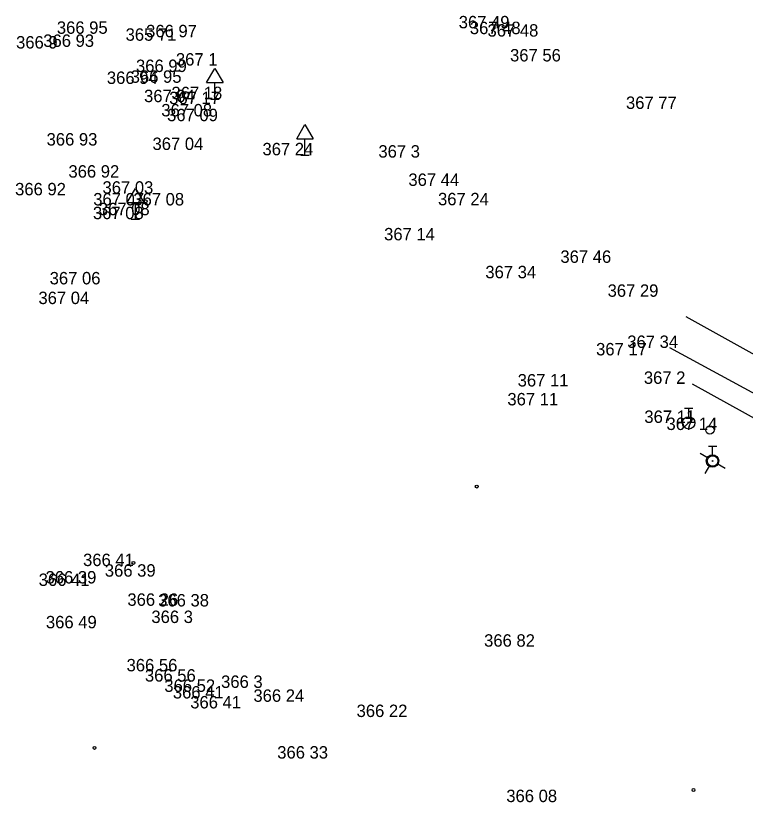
# Model space of a CAD drawing. Extents: x -688316 to -688024, y -973785 to -973591.
# Drawn here: x -688235.65 to -688191.59, y -973650.8 to -973603.28 of the extents above; entities that cross this region are included whole.
import ezdxf

# ---------------------------------------------------------------- set-up
doc = ezdxf.new("R2010")
doc.units = 0
for name, color, linetype in [('Vrstva 10', 7, 'Continuous'), ('Vrstva 28_Verejne osvetleni', 7, 'Continuous'), ('Vrstva 3', 7, 'Continuous'), ('Vrstva 34', 7, 'Continuous'), ('Vrstva 58', 7, 'Continuous'), ('Vrstva 9', 7, 'Continuous')]:
    doc.layers.add(name, color=color, linetype=linetype)

# ---------------------------------------------------------------- blocks, each defined once
blk = doc.blocks.new('B_NESP')
at = {"layer": 'Vrstva 58'}
blk.add_circle((0, 0), 0.875, dxfattribs=at)
blk = doc.blocks.new('DZ')
at = {"layer": 'Vrstva 34'}
for p, q in [((-5, 10), (0, 18.5)), ((0, 18.5), (5, 10)), ((-5, 10), (5, 10)), ((0, 0), (0, 10)), ((-2.49, 0), (2.49, 0))]:
    blk.add_line(p, q, dxfattribs=at)
blk = doc.blocks.new('HYN')
at = {"layer": 'Vrstva 28_Verejne osvetleni'}
for p, q in [((-2.5, 8.99), (2.5, 8.99)), ((0, 3.75), (0, 8.99))]:
    blk.add_line(p, q, dxfattribs=at)
blk.add_circle((0, 0), 3.75, dxfattribs=at)
blk = doc.blocks.new('SV')
at = {"layer": 'Vrstva 28_Verejne osvetleni'}
blk.add_circle((0, 0), 2.5, dxfattribs=at)
blk = doc.blocks.new('HYP')
at = {"layer": 'Vrstva 28_Verejne osvetleni'}
for p, q in [((-2.5, 8.99), (2.5, 8.99)), ((0, 3.75), (0, 8.99)), ((-2.65, -2.65), (2.65, 2.65))]:
    blk.add_line(p, q, dxfattribs=at)
blk.add_circle((0, 0), 3.75, dxfattribs=at)
blk = doc.blocks.new('HYD_1')
at = {"layer": 'Vrstva 9'}
for p, q in [((0, 13.21), (0.11, 4.83)), ((4.84, 0), (13.2, 0.01)), ((-13.16, -0.02), (-4.83, -0.01))]:
    blk.add_line(p, q, dxfattribs=at)
for radius in [4.83, 4.83, 0.333, 0.333]:
    blk.add_circle((0.01, 0), radius, dxfattribs=at)

msp = doc.modelspace()

# ---------------------------------------------------------------- linework, layer by layer
at = {"layer": 'Vrstva 10'}
for p, q in [((-688195.18, -973621.46), (-688185.33, -973626.95)), ((-688185.68, -973629.02), (-688196.14, -973623.35)), ((-688194.8, -973625.52), (-688187.63, -973629.51))]:
    msp.add_line(p, q, dxfattribs=at)

# ---------------------------------------------------------------- block references
at = {"layer": 'Vrstva 28_Verejne osvetleni', "xscale": 0.1, "yscale": 0.10000000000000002}
for name, p in [('HYP', (-688195.01, -973627.88)), ('SV', (-688193.73, -973628.31)), ('HYN', (-688193.57, -973630.18))]:
    msp.add_blockref(name, p, dxfattribs=at)
at = {"layer": 'Vrstva 34', "xscale": 0.1, "yscale": 0.10000000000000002}
for p in [(-688223.62, -973608.32), (-688223.62, -973608.32), (-688223.62, -973608.32), (-688223.62, -973608.32), (-688218.18, -973611.71), (-688218.18, -973611.71), (-688218.18, -973611.71), (-688218.18, -973611.71), (-688228.42, -973615.57), (-688228.42, -973615.57), (-688228.42, -973615.57), (-688228.42, -973615.57)]:
    msp.add_blockref('DZ', p, dxfattribs=at)
at = {"layer": 'Vrstva 58', "xscale": 0.1, "yscale": 0.10000000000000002}
for p in [(-688227.8, -973614.49), (-688227.8, -973614.49), (-688227.8, -973614.49), (-688227.8, -973614.49), (-688207.81, -973631.73), (-688207.81, -973631.73), (-688207.81, -973631.73), (-688207.81, -973631.73), (-688228.54, -973636.34), (-688228.54, -973636.34), (-688228.54, -973636.34), (-688228.54, -973636.34), (-688230.89, -973647.52), (-688230.89, -973647.52), (-688230.89, -973647.52), (-688230.89, -973647.52), (-688194.72, -973650.06), (-688194.72, -973650.06), (-688194.72, -973650.06), (-688194.72, -973650.06)]:
    msp.add_blockref('B_NESP', p, dxfattribs=at)
at = {"layer": 'Vrstva 9', "xscale": 0.06619956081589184, "yscale": 0.06619956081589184, "rotation": 149.1939737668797}
msp.add_blockref('HYD_1', (-688193.565, -973630.181), dxfattribs=at)
msp.add_blockref('HYD_1', (-688193.565, -973630.181), dxfattribs=at)

# ---------------------------------------------------------------- texts
at = {"layer": 'Vrstva 3'}
for s, p in [('367 49 ', (-688208.896, -973604.04)), ('367 49 ', (-688208.896, -973604.04)), ('367 49 ', (-688208.896, -973604.04)), ('367 49 ', (-688208.896, -973604.04)), ('367 49 ', (-688208.896, -973604.04)), ('367 49 ', (-688208.896, -973604.04)), ('367 49 ', (-688208.896, -973604.04)), ('366 95 ', (-688233.163, -973604.37)), ('366 95 ', (-688233.163, -973604.37)), ('366 95 ', (-688233.163, -973604.37)), ('366 95 ', (-688233.163, -973604.37)), ('366 95 ', (-688233.163, -973604.37)), ('366 95 ', (-688233.163, -973604.37)), ('366 95 ', (-688233.163, -973604.37)), ('366 97 ', (-688227.773, -973604.58)), ('366 97 ', (-688227.773, -973604.58)), ('366 97 ', (-688227.773, -973604.58)), ('366 97 ', (-688227.773, -973604.58)), ('366 97 ', (-688227.773, -973604.58)), ('366 97 ', (-688227.773, -973604.58)), ('366 97 ', (-688227.773, -973604.58)), ('367 48 ', (-688208.226, -973604.39)), ('367 48 ', (-688208.226, -973604.39)), ('367 48 ', (-688208.226, -973604.39)), ('367 48 ', (-688208.226, -973604.39)), ('367 48 ', (-688208.226, -973604.39)), ('367 48 ', (-688208.226, -973604.39)), ('367 48 ', (-688208.226, -973604.39)), ('367 48 ', (-688207.156, -973604.54)), ('367 48 ', (-688207.156, -973604.54)), ('367 48 ', (-688207.156, -973604.54)), ('367 48 ', (-688207.156, -973604.54)), ('367 48 ', (-688207.156, -973604.54)), ('367 48 ', (-688207.156, -973604.54)), ('367 48 ', (-688207.156, -973604.54)), ('365 71 ', (-688229.011, -973604.79)), ('365 71 ', (-688229.011, -973604.79)), ('365 71 ', (-688229.011, -973604.79)), ('365 71 ', (-688229.011, -973604.79)), ('365 71 ', (-688229.011, -973604.79)), ('365 71 ', (-688229.011, -973604.79)), ('365 71 ', (-688229.011, -973604.79)), ('366 9  ', (-688235.625, -973605.26)), ('366 9  ', (-688235.625, -973605.26)), ('366 9  ', (-688235.625, -973605.26)), ('366 9  ', (-688235.625, -973605.26)), ('366 9  ', (-688235.625, -973605.26)), ('366 9  ', (-688235.625, -973605.26)), ('366 9  ', (-688235.625, -973605.26)), ('366 93 ', (-688233.983, -973605.16)), ('366 93 ', (-688233.983, -973605.16)), ('366 93 ', (-688233.983, -973605.16)), ('366 93 ', (-688233.983, -973605.16)), ('366 93 ', (-688233.983, -973605.16)), ('366 93 ', (-688233.983, -973605.16)), ('366 93 ', (-688233.983, -973605.16)), ('367 1  ', (-688225.973, -973606.29)), ('367 1  ', (-688225.973, -973606.29)), ('367 1  ', (-688225.973, -973606.29)), ('367 1  ', (-688225.973, -973606.29)), ('367 1  ', (-688225.973, -973606.29)), ('367 1  ', (-688225.973, -973606.29)), ('367 1  ', (-688225.973, -973606.29)), ('367 56 ', (-688205.796, -973606.04)), ('367 56 ', (-688205.796, -973606.04)), ('367 56 ', (-688205.796, -973606.04)), ('367 56 ', (-688205.796, -973606.04)), ('367 56 ', (-688205.796, -973606.04)), ('367 56 ', (-688205.796, -973606.04)), ('367 56 ', (-688205.796, -973606.04)), ('366 99 ', (-688228.383, -973606.68)), ('366 99 ', (-688228.383, -973606.68)), ('366 99 ', (-688228.383, -973606.68)), ('366 99 ', (-688228.383, -973606.68)), ('366 99 ', (-688228.383, -973606.68)), ('366 99 ', (-688228.383, -973606.68)), ('366 99 ', (-688228.383, -973606.68)), ('366 94 ', (-688230.143, -973607.4)), ('366 94 ', (-688230.143, -973607.4)), ('366 94 ', (-688230.143, -973607.4)), ('366 94 ', (-688230.143, -973607.4)), ('366 94 ', (-688230.143, -973607.4)), ('366 94 ', (-688230.143, -973607.4)), ('366 94 ', (-688230.143, -973607.4)), ('366 95 ', (-688228.703, -973607.33)), ('366 95 ', (-688228.703, -973607.33)), ('366 95 ', (-688228.703, -973607.33)), ('366 95 ', (-688228.703, -973607.33)), ('366 95 ', (-688228.703, -973607.33)), ('366 95 ', (-688228.703, -973607.33)), ('366 95 ', (-688228.703, -973607.33)), ('367 18 ', (-688226.241, -973608.32)), ('367 18 ', (-688226.241, -973608.32)), ('367 18 ', (-688226.241, -973608.32)), ('367 18 ', (-688226.241, -973608.32)), ('367 18 ', (-688226.241, -973608.32)), ('367 18 ', (-688226.241, -973608.32)), ('367 18 ', (-688226.241, -973608.32)), ('367 04 ', (-688227.896, -973608.5)), ('367 04 ', (-688227.896, -973608.5)), ('367 04 ', (-688227.896, -973608.5)), ('367 04 ', (-688227.896, -973608.5)), ('367 04 ', (-688227.896, -973608.5)), ('367 04 ', (-688227.896, -973608.5)), ('367 04 ', (-688227.896, -973608.5)), ('367 17 ', (-688226.381, -973608.62)), ('367 17 ', (-688226.381, -973608.62)), ('367 17 ', (-688226.381, -973608.62)), ('367 17 ', (-688226.381, -973608.62)), ('367 17 ', (-688226.381, -973608.62)), ('367 17 ', (-688226.381, -973608.62)), ('367 17 ', (-688226.381, -973608.62)), ('367 77 ', (-688198.796, -973608.91)), ('367 77 ', (-688198.796, -973608.91)), ('367 77 ', (-688198.796, -973608.91)), ('367 77 ', (-688198.796, -973608.91)), ('367 77 ', (-688198.796, -973608.91)), ('367 77 ', (-688198.796, -973608.91)), ('367 77 ', (-688198.796, -973608.91)), ('367 08 ', (-688226.856, -973609.36)), ('367 08 ', (-688226.856, -973609.36)), ('367 08 ', (-688226.856, -973609.36)), ('367 08 ', (-688226.856, -973609.36)), ('367 08 ', (-688226.856, -973609.36)), ('367 08 ', (-688226.856, -973609.36)), ('367 08 ', (-688226.856, -973609.36)), ('367 09 ', (-688226.506, -973609.65)), ('367 09 ', (-688226.506, -973609.65)), ('367 09 ', (-688226.506, -973609.65)), ('367 09 ', (-688226.506, -973609.65)), ('367 09 ', (-688226.506, -973609.65)), ('367 09 ', (-688226.506, -973609.65)), ('367 09 ', (-688226.506, -973609.65)), ('366 93 ', (-688233.783, -973611.12)), ('366 93 ', (-688233.783, -973611.12)), ('366 93 ', (-688233.783, -973611.12)), ('366 93 ', (-688233.783, -973611.12)), ('366 93 ', (-688233.783, -973611.12)), ('366 93 ', (-688233.783, -973611.12)), ('366 93 ', (-688233.783, -973611.12)), ('367 04 ', (-688227.386, -973611.39)), ('367 04 ', (-688227.386, -973611.39)), ('367 04 ', (-688227.386, -973611.39)), ('367 04 ', (-688227.386, -973611.39)), ('367 04 ', (-688227.386, -973611.39)), ('367 04 ', (-688227.386, -973611.39)), ('367 04 ', (-688227.386, -973611.39)), ('367 24 ', (-688220.746, -973611.71)), ('367 24 ', (-688220.746, -973611.71)), ('367 24 ', (-688220.746, -973611.71)), ('367 24 ', (-688220.746, -973611.71)), ('367 24 ', (-688220.746, -973611.71)), ('367 24 ', (-688220.746, -973611.71)), ('367 24 ', (-688220.746, -973611.71)), ('367 3  ', (-688213.747, -973611.85)), ('367 3  ', (-688213.747, -973611.85)), ('367 3  ', (-688213.747, -973611.85)), ('367 3  ', (-688213.747, -973611.85)), ('367 3  ', (-688213.747, -973611.85)), ('367 3  ', (-688213.747, -973611.85)), ('367 3  ', (-688213.747, -973611.85)), ('366 92 ', (-688232.463, -973613.06)), ('366 92 ', (-688232.463, -973613.06)), ('366 92 ', (-688232.463, -973613.06)), ('366 92 ', (-688232.463, -973613.06)), ('366 92 ', (-688232.463, -973613.06)), ('366 92 ', (-688232.463, -973613.06)), ('366 92 ', (-688232.463, -973613.06)), ('367 44 ', (-688211.936, -973613.56)), ('367 44 ', (-688211.936, -973613.56)), ('367 44 ', (-688211.936, -973613.56)), ('367 44 ', (-688211.936, -973613.56)), ('367 44 ', (-688211.936, -973613.56)), ('367 44 ', (-688211.936, -973613.56)), ('367 44 ', (-688211.936, -973613.56)), ('367 03 ', (-688230.406, -973614.03)), ('367 03 ', (-688230.406, -973614.03)), ('367 03 ', (-688230.406, -973614.03)), ('367 03 ', (-688230.406, -973614.03)), ('367 03 ', (-688230.406, -973614.03)), ('367 03 ', (-688230.406, -973614.03)), ('367 03 ', (-688230.406, -973614.03)), ('366 92 ', (-688235.683, -973614.13)), ('366 92 ', (-688235.683, -973614.13)), ('366 92 ', (-688235.683, -973614.13)), ('366 92 ', (-688235.683, -973614.13)), ('366 92 ', (-688235.683, -973614.13)), ('366 92 ', (-688235.683, -973614.13)), ('366 92 ', (-688235.683, -973614.13)), ('367 07 ', (-688230.966, -973614.74)), ('367 07 ', (-688230.966, -973614.74)), ('367 07 ', (-688230.966, -973614.74)), ('367 07 ', (-688230.966, -973614.74)), ('367 07 ', (-688230.966, -973614.74)), ('367 07 ', (-688230.966, -973614.74)), ('367 07 ', (-688230.966, -973614.74)), ('367 08 ', (-688228.546, -973614.74)), ('367 08 ', (-688228.546, -973614.74)), ('367 08 ', (-688228.546, -973614.74)), ('367 08 ', (-688228.546, -973614.74)), ('367 08 ', (-688228.546, -973614.74)), ('367 08 ', (-688228.546, -973614.74)), ('367 08 ', (-688228.546, -973614.74)), ('367 24 ', (-688210.146, -973614.73)), ('367 24 ', (-688210.146, -973614.73)), ('367 24 ', (-688210.146, -973614.73)), ('367 24 ', (-688210.146, -973614.73)), ('367 24 ', (-688210.146, -973614.73)), ('367 24 ', (-688210.146, -973614.73)), ('367 24 ', (-688210.146, -973614.73)), ('367 08 ', (-688230.626, -973615.33)), ('367 08 ', (-688230.626, -973615.33)), ('367 08 ', (-688230.626, -973615.33)), ('367 08 ', (-688230.626, -973615.33)), ('367 08 ', (-688230.626, -973615.33)), ('367 08 ', (-688230.626, -973615.33)), ('367 08 ', (-688230.626, -973615.33)), ('367 08 ', (-688230.986, -973615.57)), ('367 08 ', (-688230.986, -973615.57)), ('367 08 ', (-688230.986, -973615.57)), ('367 08 ', (-688230.986, -973615.57)), ('367 08 ', (-688230.986, -973615.57)), ('367 08 ', (-688230.986, -973615.57)), ('367 08 ', (-688230.986, -973615.57)), ('367 14 ', (-688213.401, -973616.85)), ('367 14 ', (-688213.401, -973616.85)), ('367 14 ', (-688213.401, -973616.85)), ('367 14 ', (-688213.401, -973616.85)), ('367 14 ', (-688213.401, -973616.85)), ('367 14 ', (-688213.401, -973616.85)), ('367 14 ', (-688213.401, -973616.85)), ('367 46 ', (-688202.756, -973618.21)), ('367 46 ', (-688202.756, -973618.21)), ('367 46 ', (-688202.756, -973618.21)), ('367 46 ', (-688202.756, -973618.21)), ('367 46 ', (-688202.756, -973618.21)), ('367 46 ', (-688202.756, -973618.21)), ('367 46 ', (-688202.756, -973618.21)), ('367 34 ', (-688207.288, -973619.14)), ('367 34 ', (-688207.288, -973619.14)), ('367 34 ', (-688207.288, -973619.14)), ('367 34 ', (-688207.288, -973619.14)), ('367 34 ', (-688207.288, -973619.14)), ('367 34 ', (-688207.288, -973619.14)), ('367 34 ', (-688207.288, -973619.14)), ('367 06 ', (-688233.596, -973619.51)), ('367 06 ', (-688233.596, -973619.51)), ('367 06 ', (-688233.596, -973619.51)), ('367 06 ', (-688233.596, -973619.51)), ('367 06 ', (-688233.596, -973619.51)), ('367 06 ', (-688233.596, -973619.51)), ('367 06 ', (-688233.596, -973619.51)), ('367 29 ', (-688199.906, -973620.26)), ('367 29 ', (-688199.906, -973620.26)), ('367 29 ', (-688199.906, -973620.26)), ('367 29 ', (-688199.906, -973620.26)), ('367 29 ', (-688199.906, -973620.26)), ('367 29 ', (-688199.906, -973620.26)), ('367 29 ', (-688199.906, -973620.26)), ('367 04 ', (-688234.276, -973620.7)), ('367 04 ', (-688234.276, -973620.7)), ('367 04 ', (-688234.276, -973620.7)), ('367 04 ', (-688234.276, -973620.7)), ('367 04 ', (-688234.276, -973620.7)), ('367 04 ', (-688234.276, -973620.7)), ('367 04 ', (-688234.276, -973620.7)), ('367 34 ', (-688198.718, -973623.35)), ('367 34 ', (-688198.718, -973623.35)), ('367 34 ', (-688198.718, -973623.35)), ('367 34 ', (-688198.718, -973623.35)), ('367 34 ', (-688198.718, -973623.35)), ('367 34 ', (-688198.718, -973623.35)), ('367 34 ', (-688198.718, -973623.35)), ('367 17 ', (-688200.601, -973623.8)), ('367 17 ', (-688200.601, -973623.8)), ('367 17 ', (-688200.601, -973623.8)), ('367 17 ', (-688200.601, -973623.8)), ('367 17 ', (-688200.601, -973623.8)), ('367 17 ', (-688200.601, -973623.8)), ('367 17 ', (-688200.601, -973623.8)), ('367 11 ', (-688205.337, -973625.68)), ('367 11 ', (-688205.337, -973625.68)), ('367 11 ', (-688205.337, -973625.68)), ('367 11 ', (-688205.337, -973625.68)), ('367 11 ', (-688205.337, -973625.68)), ('367 11 ', (-688205.337, -973625.68)), ('367 11 ', (-688205.337, -973625.68)), ('367 2  ', (-688197.717, -973625.52)), ('367 2  ', (-688197.717, -973625.52)), ('367 2  ', (-688197.717, -973625.52)), ('367 2  ', (-688197.717, -973625.52)), ('367 2  ', (-688197.717, -973625.52)), ('367 2  ', (-688197.717, -973625.52)), ('367 2  ', (-688197.717, -973625.52)), ('367 11 ', (-688205.957, -973626.82)), ('367 11 ', (-688205.957, -973626.82)), ('367 11 ', (-688205.957, -973626.82)), ('367 11 ', (-688205.957, -973626.82)), ('367 11 ', (-688205.957, -973626.82)), ('367 11 ', (-688205.957, -973626.82)), ('367 11 ', (-688205.957, -973626.82)), ('367 11 ', (-688197.687, -973627.88)), ('367 11 ', (-688197.687, -973627.88)), ('367 11 ', (-688197.687, -973627.88)), ('367 11 ', (-688197.687, -973627.88)), ('367 11 ', (-688197.687, -973627.88)), ('367 11 ', (-688197.687, -973627.88)), ('367 11 ', (-688197.687, -973627.88)), ('367 14 ', (-688196.351, -973628.31)), ('367 14 ', (-688196.351, -973628.31)), ('367 14 ', (-688196.351, -973628.31)), ('367 14 ', (-688196.351, -973628.31)), ('367 14 ', (-688196.351, -973628.31)), ('367 14 ', (-688196.351, -973628.31)), ('367 14 ', (-688196.351, -973628.31)), ('366 41 ', (-688231.579, -973636.53)), ('366 41 ', (-688231.579, -973636.53)), ('366 41 ', (-688231.579, -973636.53)), ('366 41 ', (-688231.579, -973636.53)), ('366 41 ', (-688231.579, -973636.53)), ('366 41 ', (-688231.579, -973636.53)), ('366 41 ', (-688231.579, -973636.53)), ('366 39 ', (-688230.265, -973637.17)), ('366 39 ', (-688230.265, -973637.17)), ('366 39 ', (-688230.265, -973637.17)), ('366 39 ', (-688230.265, -973637.17)), ('366 39 ', (-688230.265, -973637.17)), ('366 39 ', (-688230.265, -973637.17)), ('366 39 ', (-688230.265, -973637.17)), ('366 41 ', (-688234.259, -973637.73)), ('366 41 ', (-688234.259, -973637.73)), ('366 41 ', (-688234.259, -973637.73)), ('366 41 ', (-688234.259, -973637.73)), ('366 41 ', (-688234.259, -973637.73)), ('366 41 ', (-688234.259, -973637.73)), ('366 41 ', (-688234.259, -973637.73)), ('366 39 ', (-688233.845, -973637.58)), ('366 39 ', (-688233.845, -973637.58)), ('366 39 ', (-688233.845, -973637.58)), ('366 39 ', (-688233.845, -973637.58)), ('366 39 ', (-688233.845, -973637.58)), ('366 39 ', (-688233.845, -973637.58)), ('366 39 ', (-688233.845, -973637.58)), ('366 26 ', (-688228.903, -973638.93)), ('366 26 ', (-688228.903, -973638.93)), ('366 26 ', (-688228.903, -973638.93)), ('366 26 ', (-688228.903, -973638.93)), ('366 26 ', (-688228.903, -973638.93)), ('366 26 ', (-688228.903, -973638.93)), ('366 26 ', (-688228.903, -973638.93)), ('366 38 ', (-688227.045, -973638.97)), ('366 38 ', (-688227.045, -973638.97)), ('366 38 ', (-688227.045, -973638.97)), ('366 38 ', (-688227.045, -973638.97)), ('366 38 ', (-688227.045, -973638.97)), ('366 38 ', (-688227.045, -973638.97)), ('366 38 ', (-688227.045, -973638.97)), ('366 3  ', (-688227.455, -973639.97)), ('366 3  ', (-688227.455, -973639.97)), ('366 3  ', (-688227.455, -973639.97)), ('366 3  ', (-688227.455, -973639.97)), ('366 3  ', (-688227.455, -973639.97)), ('366 3  ', (-688227.455, -973639.97)), ('366 3  ', (-688227.455, -973639.97)), ('366 49 ', (-688233.823, -973640.29)), ('366 49 ', (-688233.823, -973640.29)), ('366 49 ', (-688233.823, -973640.29)), ('366 49 ', (-688233.823, -973640.29)), ('366 49 ', (-688233.823, -973640.29)), ('366 49 ', (-688233.823, -973640.29)), ('366 49 ', (-688233.823, -973640.29)), ('366 82 ', (-688207.363, -973641.4)), ('366 82 ', (-688207.363, -973641.4)), ('366 82 ', (-688207.363, -973641.4)), ('366 82 ', (-688207.363, -973641.4)), ('366 82 ', (-688207.363, -973641.4)), ('366 82 ', (-688207.363, -973641.4)), ('366 82 ', (-688207.363, -973641.4)), ('366 56 ', (-688228.953, -973642.89)), ('366 56 ', (-688228.953, -973642.89)), ('366 56 ', (-688228.953, -973642.89)), ('366 56 ', (-688228.953, -973642.89)), ('366 56 ', (-688228.953, -973642.89)), ('366 56 ', (-688228.953, -973642.89)), ('366 56 ', (-688228.953, -973642.89)), ('366 56 ', (-688227.843, -973643.51)), ('366 56 ', (-688227.843, -973643.51)), ('366 56 ', (-688227.843, -973643.51)), ('366 56 ', (-688227.843, -973643.51)), ('366 56 ', (-688227.843, -973643.51)), ('366 56 ', (-688227.843, -973643.51)), ('366 56 ', (-688227.843, -973643.51)), ('366 3  ', (-688223.245, -973643.89)), ('366 3  ', (-688223.245, -973643.89)), ('366 3  ', (-688223.245, -973643.89)), ('366 3  ', (-688223.245, -973643.89)), ('366 3  ', (-688223.245, -973643.89)), ('366 3  ', (-688223.245, -973643.89)), ('366 3  ', (-688223.245, -973643.89)), ('366 52 ', (-688226.673, -973644.13)), ('366 52 ', (-688226.673, -973644.13)), ('366 52 ', (-688226.673, -973644.13)), ('366 52 ', (-688226.673, -973644.13)), ('366 52 ', (-688226.673, -973644.13)), ('366 52 ', (-688226.673, -973644.13)), ('366 52 ', (-688226.673, -973644.13)), ('366 41 ', (-688226.159, -973644.53)), ('366 41 ', (-688226.159, -973644.53)), ('366 41 ', (-688226.159, -973644.53)), ('366 41 ', (-688226.159, -973644.53)), ('366 41 ', (-688226.159, -973644.53)), ('366 41 ', (-688226.159, -973644.53)), ('366 41 ', (-688226.159, -973644.53)), ('366 24 ', (-688221.293, -973644.73)), ('366 24 ', (-688221.293, -973644.73)), ('366 24 ', (-688221.293, -973644.73)), ('366 24 ', (-688221.293, -973644.73)), ('366 24 ', (-688221.293, -973644.73)), ('366 24 ', (-688221.293, -973644.73)), ('366 24 ', (-688221.293, -973644.73)), ('366 41 ', (-688225.109, -973645.13)), ('366 41 ', (-688225.109, -973645.13)), ('366 41 ', (-688225.109, -973645.13)), ('366 41 ', (-688225.109, -973645.13)), ('366 41 ', (-688225.109, -973645.13)), ('366 41 ', (-688225.109, -973645.13)), ('366 41 ', (-688225.109, -973645.13)), ('366 22 ', (-688215.063, -973645.65)), ('366 22 ', (-688215.063, -973645.65)), ('366 22 ', (-688215.063, -973645.65)), ('366 22 ', (-688215.063, -973645.65)), ('366 22 ', (-688215.063, -973645.65)), ('366 22 ', (-688215.063, -973645.65)), ('366 22 ', (-688215.063, -973645.65)), ('366 33 ', (-688219.855, -973648.16)), ('366 33 ', (-688219.855, -973648.16)), ('366 33 ', (-688219.855, -973648.16)), ('366 33 ', (-688219.855, -973648.16)), ('366 33 ', (-688219.855, -973648.16)), ('366 33 ', (-688219.855, -973648.16)), ('366 33 ', (-688219.855, -973648.16)), ('366 08 ', (-688206.023, -973650.79)), ('366 08 ', (-688206.023, -973650.79)), ('366 08 ', (-688206.023, -973650.79)), ('366 08 ', (-688206.023, -973650.79)), ('366 08 ', (-688206.023, -973650.79)), ('366 08 ', (-688206.023, -973650.79)), ('366 08 ', (-688206.023, -973650.79))]:
    msp.add_text(s, height=0.75, dxfattribs=at).set_placement(p)

doc.saveas('drawing.dxf')
